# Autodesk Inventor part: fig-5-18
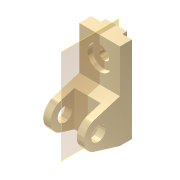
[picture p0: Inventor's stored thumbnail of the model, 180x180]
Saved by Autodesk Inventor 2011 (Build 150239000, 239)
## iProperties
Shininess: 65.0
Angle Display Precision: 2
Document Length Units: 11269
Document Angle Units: 11279
Document Time Units: 11290
Document Mass Units: 11283
Document Length Units Precision: 3
Document Angle Units Precision: 2
Compacted: False
Created: 2001-11
Part Number: fig-5-18
Document SubType Name: Modeling
Designer: Renu Muthoo
Density: 1 g/cm^3
Density: 0.0
Volumn: 0.0
Area: 0.0
PropertySet Name: Model Information
Control State: 0
Master: False
Checked Out: False
Author: Renu Muthoo
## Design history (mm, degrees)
node "Sketch1"
sketch "Sketch2"
  geometry: L1 (33.257, 104.664)-(33.257, -75.336); L2 (33.257, -75.336)-(8.257, -75.336); L3 (8.257, -75.336)-(-45.451, -59.045); L4 (-45.451, -1.628)-(8.257, 14.664); L5 (8.257, 14.664)-(8.257, 104.664); L6 (8.257, 104.664)-(33.257, 104.664); C1 r 15 at (-36.743, -30.336); A1 r 30 centre (-36.743, -30.336) between (-45.451, -1.628) and (-45.451, -59.045)
  constraints: 12 end point, 2 centre point, 2 equal length, 2 parallel, 2 point on circle, 2 tangent, 1 coincident, 1 perpendicular, 1 vertical
  dimensions: "d0" = 180 distance of L1.start L1.end; "d1" = 30 radius of A1; "d2" = 25 distance of L5.end L1.start; "d3" = 45 distance from line of L2 A1.centre; "d4" = 70 distance from line of L1 A1.centre; "d5" = 30 diameter of C1
extrude "Extrusion1" new body sketch "Sketch2" distance "d6" = 85; taper "d7" = 0 deg
workplane "Work Plane1"
sketch "Sketch3"
  geometry: L1 (15, 62.364)-(70, 62.364); L2 (70, 62.364)-(70, -52.386); L3 (70, -52.386)-(15, -52.386); L4 (15, -52.386)-(15, 62.364); L5 (0, -45)-(0, -28.708) reference
  constraints: 8 end point, 2 parallel, 1 horizontal, 1 perpendicular
  dimensions: "d8" = 55 distance of L1.start L1.end; "d9" = 15 distance between parallel lines of L5 L4
extrude "Extrusion2" cut sketch "Sketch3" distance "d10" = 50; taper "d11" = 0 deg
sketch "Sketch4"
  geometry: L1 (0, 25)-(85, 25) reference; L2 (0, 0)-(0, 25) reference; L3 (20, 25)-(65, 25); L4 (65, 25)-(65, 35); L5 (65, 35)-(20, 35); L6 (20, 35)-(20, 25)
  constraints: 8 end point, 2 parallel, 1 horizontal, 1 perpendicular, 1 point on line
  dimensions: "d12" = 45 distance of L4.end L5.end; "d13" = 10 distance of L3.end L4.end; "d14" = 20 distance between parallel lines of L2 L6
extrude "Extrusion3" join sketch "Sketch4" stored distance "d15" = 50; taper "d16" = 0 deg
sketch "Sketch5"
  geometry: L1 (85, 0)-(85, 90) reference; L2 (0, 90)-(85, 90) reference; 1 further point
  dimensions: "d17" = 42 distance from line of L2 point (42.5, 48); "d18" = 42.5 distance from line of L1 point (42.5, 48)
hole "Hole1" sketch "Sketch5" at (42.5, 48) diameter "d19" = 20; stored, may be unused: countersink angle "d23" = 82 deg, drill point angle "d25" = 118 deg; dims "d20" = 6, "d21" = 50, "d22" = 10, "d24" = 8
workplane "Work Plane9"
body "Solid1"
